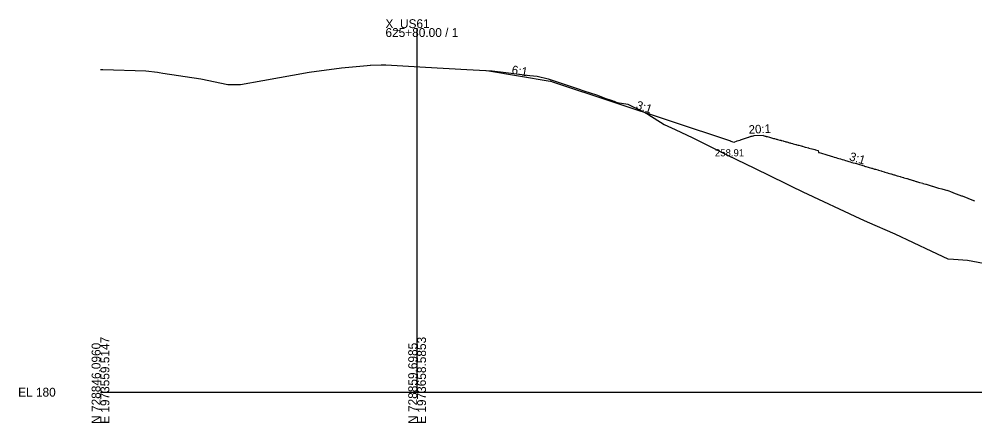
# Model space of a CAD drawing. Extents: x -26 to 630, y -39 to 9098.
# Drawn here: x -25.7 to 276.1, y 4490.3 to 4617.8 of the extents above; entities that cross this region are included whole.
import ezdxf

# ---------------------------------------------------------------- set-up
doc = ezdxf.new("R2010")
doc.units = 0
for name, color, linetype in [('CONST_DCH', 7, 'Continuous'), ('Draft_XS_Grid', 7, 'Continuous'), ('DTM CONTOURS_MAJOR', 7, 'Continuous'), ('DTM_X_GROUND', 7, 'Continuous'), ('X_DTM_CONTOURS_MAJOR', 7, 'Continuous'), ('XS_CELL', 7, 'Continuous'), ('XS_P_GROUND', 7, 'Continuous'), ('XS_P_TX_DCH', 7, 'Continuous'), ('XS_P_TX_FS_BS', 7, 'Continuous')]:
    doc.layers.add(name, color=color, linetype=linetype)

msp = doc.modelspace()

# ---------------------------------------------------------------- linework, layer by layer
at = {"layer": 'DTM_X_GROUND'}
msp.add_lwpolyline([(0, 4601.96), (0.31, 4601.96), (0.76, 4601.94), (14.34, 4601.46), (18.05, 4601.06), (18.56, 4601.01), (19.72, 4600.82), (31.74, 4598.97), (40.23, 4597.19), (44.27, 4597.17), (51.31, 4598.47), (65.86, 4601.11), (76.1, 4602.47), (84.18, 4603.22), (85.13, 4603.3), (85.27, 4603.31), (88.69, 4603.44), (90.07, 4603.37), (102.6, 4602.71), (115.66, 4601.95), (123.66, 4601.48), (124.58, 4601.37), (126.37, 4601.16), (135.59, 4600.05), (137.93, 4599.77), (141.35, 4598.98), (150.82, 4595.82), (152.68, 4595.2), (156.61, 4593.9), (159.64, 4592.81), (161.27, 4592.22), (162.09, 4591.93), (162.19, 4591.89), (162.65, 4591.73), (162.88, 4591.65), (163.16, 4591.54), (163.22, 4591.52), (166.57, 4590.98), (170.89, 4588.9), (172.89, 4587.78), (177.99, 4584.58), (181.5, 4583), (187.02, 4580.39), (198.03, 4574.89), (206.51, 4570.71), (216.48, 4565.87), (218.11, 4565.08), (221.78, 4563.33), (239.75, 4554.87), (242.09, 4553.86), (250.89, 4550.03), (262.42, 4544.54), (267.55, 4542.08), (269.33, 4542), (273.79, 4541.71), (282.72, 4539.98)], dxfattribs=at)
at = {"layer": 'XS_CELL'}
for p, q in [((100, 4500), (100, 4615)), ((0, 4500), (100, 4500)), ((100, 4500), (450, 4500))]:
    msp.add_line(p, q, dxfattribs=at)
at = {"layer": 'XS_P_GROUND'}
for points in [[(122, 4601.58), (142, 4598.24)], [(209.31, 4581.08), (206.32, 4580.93), (206.08, 4580.91), (206.01, 4580.91), (206, 4580.91), (205.66, 4580.8), (205.62, 4580.78), (205.61, 4580.78), (205.42, 4580.72), (204.6, 4580.44), (204.56, 4580.43), (202.04, 4579.59), (201.88, 4579.54), (201.1, 4579.28), (201, 4579.24), (200, 4578.91), (199.5, 4579.08), (199.17, 4579.19), (199.13, 4579.2), (199.03, 4579.23), (199.02, 4579.24), (143.2, 4597.84), (142, 4598.24)], [(209.31, 4581.08), (209.55, 4581.01), (209.59, 4581), (209.93, 4580.9), (210.1, 4580.86), (210.26, 4580.81), (210.56, 4580.73), (211.24, 4580.55), (211.56, 4580.46), (212.21, 4580.28), (212.56, 4580.18), (212.86, 4580.1), (213.43, 4579.95), (213.52, 4579.92), (213.56, 4579.91), (213.84, 4579.83), (214.57, 4579.63), (214.82, 4579.56), (214.94, 4579.53), (215.14, 4579.48), (215.57, 4579.36), (215.79, 4579.3), (216.2, 4579.19), (216.44, 4579.12), (216.57, 4579.08), (216.76, 4579.03), (217.58, 4578.81), (217.74, 4578.76), (217.82, 4578.74), (218.06, 4578.67), (218.58, 4578.53), (218.71, 4578.5), (219.58, 4578.26), (219.68, 4578.23), (219.87, 4578.18), (220.33, 4578.05), (220.58, 4577.98), (221.3, 4577.78), (221.59, 4577.71), (221.63, 4577.7), (221.7, 4577.68), (222.27, 4577.52), (222.59, 4577.43), (222.62, 4577.42), (223.59, 4577.16), (223.7, 4577.13), (224.6, 4576.88), (224.77, 4576.83), (225.6, 4576.61), (225.84, 4576.54), (226.6, 4576.33), (226.71, 4575.75), (226.71, 4575.75), (226.71, 4575.75), (226.71, 4575.75), (226.71, 4575.75), (226.71, 4575.75), (226.98, 4575.67), (227.71, 4575.45), (228.02, 4575.36), (228.71, 4575.16), (229.07, 4575.05), (229.71, 4574.86), (230.11, 4574.74), (230.71, 4574.56), (231.14, 4574.44), (231.71, 4574.27), (232.18, 4574.13), (232.71, 4573.97), (233.21, 4573.82), (233.71, 4573.67), (234.24, 4573.52), (234.71, 4573.38), (235.27, 4573.21), (235.71, 4573.08), (236.3, 4572.91), (236.71, 4572.79), (237.32, 4572.6), (237.71, 4572.49), (238.34, 4572.3), (238.71, 4572.19), (239.37, 4572), (239.71, 4571.9), (240.39, 4571.7), (240.71, 4571.6), (241.13, 4571.47), (241.32, 4571.42), (241.6, 4571.34), (241.71, 4571.3), (242.43, 4571.09), (242.71, 4571.01), (243.45, 4570.79), (243.71, 4570.71), (244.46, 4570.49), (244.71, 4570.41), (245.48, 4570.19), (245.71, 4570.12), (246.5, 4569.88), (246.71, 4569.82), (247.51, 4569.58), (247.71, 4569.52), (248.52, 4569.28), (248.71, 4569.23), (249.54, 4568.98), (249.71, 4568.93), (250.55, 4568.68), (250.71, 4568.63), (251.56, 4568.38), (251.71, 4568.34), (252.58, 4568.08), (252.71, 4568.04), (253.59, 4567.78), (253.71, 4567.75), (254.6, 4567.48), (254.71, 4567.45), (255.61, 4567.18), (255.71, 4567.15), (256.62, 4566.88), (256.71, 4566.86), (257.63, 4566.58), (257.71, 4566.56), (258.64, 4566.28), (258.71, 4566.26), (259.65, 4565.99), (259.71, 4565.97), (260.66, 4565.69), (260.71, 4565.67), (261.66, 4565.39), (261.71, 4565.37), (262.67, 4565.09), (262.71, 4565.08), (263.68, 4564.79), (263.71, 4564.78), (264.69, 4564.49), (264.71, 4564.48), (265.7, 4564.19), (265.71, 4564.19), (266.71, 4563.89), (266.71, 4563.89), (267.45, 4563.67)], [(267.98, 4563.47), (267.45, 4563.67)], [(270.04, 4562.69), (268.51, 4563.27), (267.98, 4563.47)], [(271.98, 4561.96), (270.38, 4562.57), (270.04, 4562.69)], [(274.04, 4561.18), (272.22, 4561.87), (271.98, 4561.96)], [(276.13, 4560.39), (274.23, 4561.11), (274.04, 4561.18)]]:
    msp.add_lwpolyline(points, dxfattribs=at)

# ---------------------------------------------------------------- texts
at = {"layer": 'CONST_DCH'}
for p in [(209.31, 4581.07), (267.45, 4563.67)]:
    msp.add_text('X', height=0.001, dxfattribs=at).set_placement(p)
at = {"layer": 'Draft_XS_Grid'}
msp.add_text('-', height=0.0001, dxfattribs=at).set_placement((0, 4500))
at = {"layer": 'DTM CONTOURS_MAJOR'}
msp.add_text('X', height=0.001, dxfattribs=at).set_placement((200, 4578.91))
at = {"layer": 'X_DTM_CONTOURS_MAJOR'}
for p in [(122, 4601.58), (142, 4598.24), (206, 4580.91)]:
    msp.add_text('X', height=0.001, dxfattribs=at).set_placement(p)
at = {"layer": 'XS_CELL'}
for s, p in [('X_US61', (90, 4615)), ('625+80.00 / 1', (90, 4612.2)), ('EL 180', (-26, 4498.6))]:
    msp.add_text(s, height=2.8, dxfattribs=at).set_placement(p)
for s, p in [('N 728846.0960', (0, 4490)), ('E 1973559.5147', (2.8, 4490)), ('N 728859.6985', (100, 4490)), ('E 1973658.5853', (102.8, 4490))]:
    msp.add_text(s, height=2.8, rotation=90, dxfattribs=at).set_placement(p)
at = {"layer": 'XS_P_TX_DCH'}
msp.add_text('258.91', height=2.25, dxfattribs=at).set_placement((194.05, 4574.5))
at = {"layer": 'XS_P_TX_FS_BS'}
for s, rotation, p in [('6:1', 350.5377, (129.72, 4600.59)), ('3:1', 341.5651, (168.92, 4589.59)), ('20:1', 2.8625, (204.76, 4581.6)), ('3:1', 343.337, (236.27, 4573.32))]:
    msp.add_text(s, height=2.7, rotation=rotation, dxfattribs=at).set_placement(p)

doc.saveas('drawing.dxf')
